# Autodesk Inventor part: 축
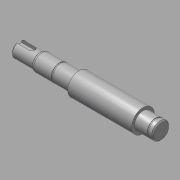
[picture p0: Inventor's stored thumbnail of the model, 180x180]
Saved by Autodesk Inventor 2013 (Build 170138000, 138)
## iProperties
Created: 2015-12
Part Number: 축
Material: 강철, 연강
Document SubType Name: Modeling
Designer: mduedu
Density: 7.86 g/cm^3
Author: mduedu
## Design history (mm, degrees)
sketch "스케치1"
  geometry: L1 (-62.5, 0)-(62.5, 0); L2 (-62.5, 0)-(-62.5, 6.5); L3 (-62.5, 6.5)-(-43.5, 6.5); L4 (-43.5, 7)-(-42.634, 7.5); L5 (-42.634, 7.5)-(-9.5, 7.5); L6 (-9.5, 7.5)-(-9.5, 10); L7 (-9.5, 10)-(46.5, 10); L8 (46.5, 10)-(46.5, 7.5); L9 (46.5, 7.5)-(62.5, 7.5); L10 (62.5, 7.5)-(62.5, 0); L11 (-43.5, 6.5)-(-43.5, 7); 2 further points
  constraints: 22 end point, 6 parallel, 2 perpendicular, 1 coincident, 1 horizontal, 1 midpoint, 1 vertical
  dimensions: "d0" = 13 diameter of L3 L1; "d2" = 15 diameter of L5 L1; "d3" = 20 diameter of L7 L1; "d5" = 15 diameter of L9 L1; "d6" = 125 distance of L1.start L1.end; "d7" = 19 distance of L2.end L3.end; "d8" = 34 distance from line of L6 L3.end; "d9" = 56 distance of L6.end L7.end; "d41" = 14 diameter of L4.start L1; "d42" = 30 deg angle of L4 L3
revolve "회전1" sketch "스케치1" stored, may be unused: angle "d11" = 90 deg
node "작업 평면1"
node "작업 평면2"
sketch "스케치3"
  geometry: L1 (9.5, -2.5)-(-2.5, -2.5); L2 (-2.5, 2.5)-(9.5, 2.5); L3 (9.5, 2.5)-(9.5, -2.5); L4 (9.5, 6.5)-(9.5, -6.5) reference; A1 r 2.5 centre (-2.5, 0) between (-2.5, 2.5) and (-2.5, -2.5); 1 further point
  constraints: 6 end point, 2 point on circle, 2 tangent, 1 centre point, 1 collinear, 1 horizontal, 1 horizontal alignment, 1 parallel
  dimensions: "d17" = 5 distance of L2.end L1.start; "d19" = 12 distance from line of A1.centre L3
extrude "돌출2" cut sketch "스케치3" distance "d20" = 3; taper "d21" = 0 deg
chamfer "모따기1" distance "d22" = 1; stored, may be unused: second distance "d23" = 2, angle "d24" = 45 deg
fillet "모깎기1" dims "d25" = 3
sketch "스케치4"
  geometry: L1 (-9.5, -10)-(-9.5, 10) reference; L2 (-9.5, 0)-(0, 0); L3 (-26.65, 12.15)-(-25.5, 12.15); L4 (-25.5, 12.15)-(-25.5, 7.15); L5 (-25.5, 7.15)-(-26.65, 7.15); L6 (-26.65, 7.15)-(-26.65, 12.15); L7 (57.5, 12.15)-(58.65, 12.15); L8 (58.65, 12.15)-(58.65, 7.15); L9 (58.65, 7.15)-(57.5, 7.15); L10 (57.5, 7.15)-(57.5, 12.15); L11 (62.5, -7.5)-(62.5, 7.5) reference
  constraints: 18 end point, 4 parallel, 2 horizontal, 2 perpendicular, 1 midpoint
  dimensions: "d26" = 16 distance between parallel lines of L4 L1; "d27" = 1.15 distance of L3.start L3.end; "d28" = 14.3 diameter of L5 L2; "d29" = 5 distance of L3.end L4.end; "d30" = 1.15 distance of L7.start L7.end; "d31" = 5 distance of L7.end L8.end; "d32" = 5 distance between parallel lines of L10 L11; "d33" = 14.3 diameter of L9 L2
revolve "회전2" sketch "스케치4" stored, may be unused: angle "d34" = 90 deg
chamfer "모따기2" distance "d35" = 1; stored, may be unused: second distance "d36" = 2, angle "d37" = 45 deg
sketch "스케치5"
  geometry: 2 further points
  constraints: 1 coincident
sketch "스케치6"
  geometry: 1 further point
hole "구멍1" sketch "스케치6" at (2.5, -3.5) diameter "d43" = 4.917; stored, may be unused: countersink angle "d47" = 90 deg, drill point angle "d49" = 120 deg; dims "d44" = 14, "d45" = 4, "d46" = 2, "d48" = 17
node "솔리드1"
other parameters: "d12" = -15.5
